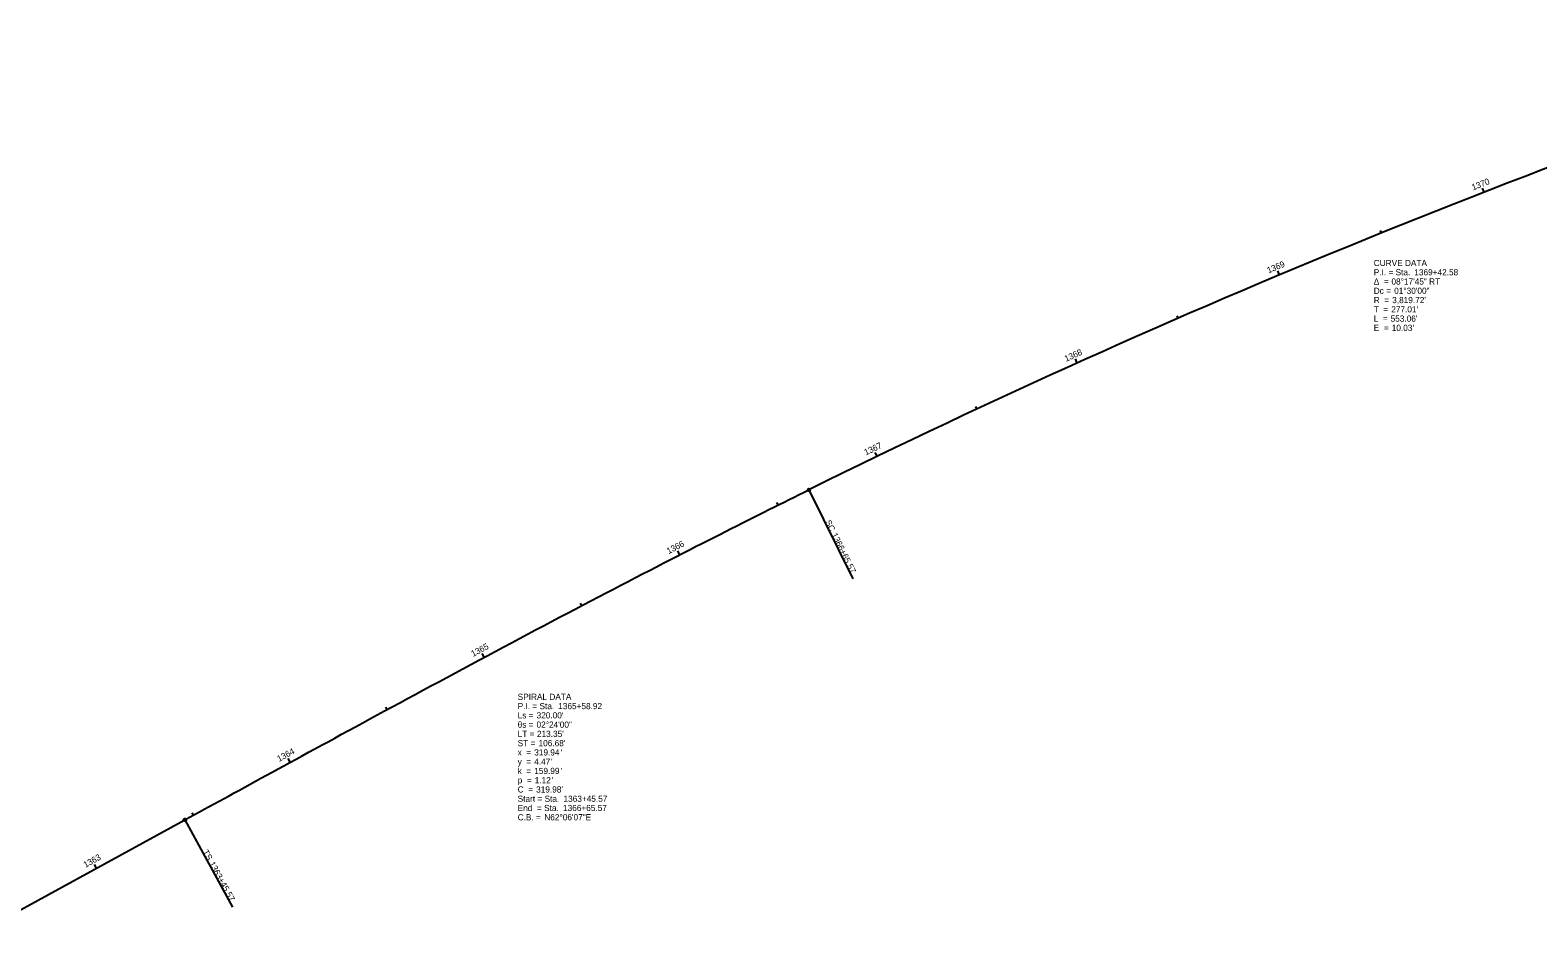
# Model space of a CAD drawing. Extents: x 153500 to 156291, y 370917 to 372075.
# Drawn here: x 154193 to 154876, y 371277 to 371682 of the extents above; entities that cross this region are included whole.
import ezdxf

# ---------------------------------------------------------------- set-up
doc = ezdxf.new("R2010")
doc.units = 0
for name, color, linetype in [('Default', 7, 'Continuous'), ('GE_X_Alignment', 7, 'Continuous'), ('GE_X_Alignment_1000_Curve_Data', 7, 'Continuous'), ('GE_X_Alignment_1000_Stations', 7, 'Continuous'), ('GE_X_Alignment_100_Curve_Data', 7, 'Continuous'), ('GE_X_Alignment_100_Stations', 7, 'Continuous'), ('GE_X_Alignment_500_Curve_Data', 7, 'Continuous'), ('GE_X_Alignment_500_Stations', 7, 'Continuous')]:
    doc.layers.add(name, color=color, linetype=linetype)

msp = doc.modelspace()

# ---------------------------------------------------------------- linework, layer by layer
at = {"layer": 'Default'}
msp.add_line((153521.23, 370917.9), (154262.92, 371323.93), dxfattribs=at)
msp.add_arc((156238, 368049.26), 3819.72, 108.0022, 116.29803, dxfattribs=at)
msp.add_open_spline([(154262.92, 371323.93), (154274.62, 371330.33), (154298.01, 371343.14), (154344.82, 371368.69), (154403.47, 371400.39), (154462.44, 371431.49), (154509.91, 371455.8), (154533.76, 371467.74), (154545.71, 371473.65)], degree=3, dxfattribs=at)
at = {"layer": 'GE_X_Alignment'}
msp.add_line((153521.23, 370917.9), (154262.92, 371323.93), dxfattribs=at)
msp.add_arc((156238, 368049.26), 3819.72, 108.0022, 116.29803, dxfattribs=at)
msp.add_open_spline([(154262.92, 371323.93), (154274.62, 371330.33), (154298.01, 371343.14), (154344.82, 371368.69), (154403.47, 371400.39), (154462.44, 371431.49), (154509.91, 371455.8), (154533.76, 371467.74), (154545.71, 371473.65)], degree=3, dxfattribs=at)
at = {"layer": 'GE_X_Alignment_1000_Stations'}
for p, q in [((154851.63, 371608.51), (154850.9, 371610.37)), ((154545.71, 371473.65), (154565.65, 371433.3)), ((154398.62, 371397.65), (154398.06, 371398.7)), ((154262.92, 371323.93), (154284.53, 371284.46))]:
    msp.add_line(p, q, dxfattribs=at)
for centre in [(154545.71, 371473.65), (154262.92, 371323.93)]:
    msp.add_circle(centre, 0.6, dxfattribs=at)
at = {"layer": 'GE_X_Alignment_100_Stations'}
for p, q in [((154851.63, 371608.51), (154850.9, 371610.37)), ((154805.16, 371590.06), (154804.71, 371591.17)), ((154758.93, 371571), (154758.16, 371572.84)), ((154712.96, 371551.33), (154712.48, 371552.43)), ((154667.25, 371531.07), (154666.43, 371532.9)), ((154621.81, 371510.21), (154621.3, 371511.3)), ((154576.65, 371488.76), (154575.78, 371490.56)), ((154545.71, 371473.65), (154565.65, 371433.3)), ((154531.77, 371466.72), (154531.23, 371467.79)), ((154487.16, 371444.13), (154486.25, 371445.91)), ((154442.8, 371421.07), (154442.24, 371422.13)), ((154398.62, 371397.65), (154397.68, 371399.41)), ((154354.6, 371373.94), (154354.03, 371375)), ((154310.68, 371350.05), (154309.72, 371351.8)), ((154262.92, 371323.93), (154284.53, 371284.46)), ((154266.81, 371326.06), (154266.23, 371327.11)), ((154222.95, 371302.05), (154221.99, 371303.8))]:
    msp.add_line(p, q, dxfattribs=at)
for centre in [(154545.71, 371473.65), (154262.92, 371323.93)]:
    msp.add_circle(centre, 0.6, dxfattribs=at)
at = {"layer": 'GE_X_Alignment_500_Stations'}
for p, q in [((154851.63, 371608.51), (154850.9, 371610.37)), ((154758.93, 371571), (154758.47, 371572.1)), ((154667.25, 371531.07), (154666.76, 371532.17)), ((154576.65, 371488.76), (154576.12, 371489.84)), ((154545.71, 371473.65), (154565.65, 371433.3)), ((154487.16, 371444.13), (154486.61, 371445.2)), ((154398.62, 371397.65), (154397.68, 371399.41)), ((154310.68, 371350.05), (154310.1, 371351.1)), ((154262.92, 371323.93), (154284.53, 371284.46)), ((154222.95, 371302.05), (154222.37, 371303.1))]:
    msp.add_line(p, q, dxfattribs=at)
for centre in [(154545.71, 371473.65), (154262.92, 371323.93)]:
    msp.add_circle(centre, 0.6, dxfattribs=at)

# ---------------------------------------------------------------- texts
at = {"layer": 'GE_X_Alignment_1000_Curve_Data'}
for s, p in [('CURVE DATA', (154801.61, 371575.02)), ('Δ  = ', (154801.61, 371566.62)), ('P.I. = Sta. ', (154801.61, 371570.82)), ('08°17\'45" RT', (154809.63, 371566.62)), ('1369+42.58', (154819.98, 371570.82)), ('Dc = ', (154801.61, 371562.42)), ('01°30\'00"', (154810.85, 371562.42)), ('T  = ', (154801.61, 371554.02)), ('R  = ', (154801.61, 371558.22)), ("277.01'", (154809.54, 371554.02)), ("3,819.72'", (154809.97, 371558.22)), ('L  = ', (154801.61, 371549.82)), ('E  = ', (154801.61, 371545.62)), ("553.06'", (154809.25, 371549.82)), ("10.03'", (154809.76, 371545.62)), ('SPIRAL DATA', (154413.74, 371378.35)), ('P.I. = Sta. ', (154413.74, 371374.15)), ('Ls = ', (154413.74, 371369.95)), ("320.00'", (154422.32, 371369.95)), ('1365+58.92', (154432.1, 371374.15)), ('θs = ', (154413.74, 371365.75)), ('LT = ', (154413.74, 371361.55)), ('02°24\'00"', (154422.27, 371365.75)), ("213.35'", (154422.47, 371361.55)), ('ST = ', (154413.74, 371357.35)), ("106.68'", (154423.19, 371357.35)), ('y  = ', (154413.74, 371348.95)), ('x  = ', (154413.74, 371353.15)), ('4.47', (154421.24, 371348.95)), ('319.94', (154421.24, 371353.15)), ("'", (154428.85, 371348.95)), ("'", (154433.2, 371353.15)), ('k  = ', (154413.74, 371344.75)), ('159.99', (154421.24, 371344.75)), ('1.12', (154421.45, 371340.55)), ("'", (154429.06, 371340.55)), ("'", (154433.2, 371344.75)), ('C  = ', (154413.74, 371336.35)), ('p  = ', (154413.74, 371340.55)), ("319.98'", (154422.1, 371336.35)), ('Start = Sta. ', (154413.74, 371332.15)), ('End  = Sta. ', (154413.74, 371327.95)), ('1366+65.57', (154434.28, 371327.95)), ('1363+45.57', (154434.5, 371332.15)), ('C.B. = ', (154413.74, 371323.75)), ('N62°06\'07"E', (154425.8, 371323.75))]:
    msp.add_text(s, height=2.8, dxfattribs=at).set_placement(p)
at = {"layer": 'GE_X_Alignment_1000_Stations'}
for s, rotation, p in [('1370', 21.28158, (154846.63, 371609.3)), ('SC', 296.29803, (154552.96, 371459.07)), ('1366+65.57', 296.29803, (154555.85, 371453.23)), ('TS', 298.69803, (154270.89, 371309.48)), ('1363+45.57', 298.69803, (154273.81, 371304.14))]:
    msp.add_text(s, height=2.8, rotation=rotation, dxfattribs=at).set_placement(p)
at = {"layer": 'GE_X_Alignment_100_Curve_Data'}
for s, p in [('CURVE DATA', (154801.61, 371575.02)), ('Δ  = ', (154801.61, 371566.62)), ('P.I. = Sta. ', (154801.61, 371570.82)), ('08°17\'45" RT', (154809.63, 371566.62)), ('1369+42.58', (154819.98, 371570.82)), ('Dc = ', (154801.61, 371562.42)), ('01°30\'00"', (154810.85, 371562.42)), ('T  = ', (154801.61, 371554.02)), ('R  = ', (154801.61, 371558.22)), ("277.01'", (154809.54, 371554.02)), ("3,819.72'", (154809.97, 371558.22)), ('L  = ', (154801.61, 371549.82)), ('E  = ', (154801.61, 371545.62)), ("553.06'", (154809.25, 371549.82)), ("10.03'", (154809.76, 371545.62)), ('SPIRAL DATA', (154413.74, 371378.35)), ('P.I. = Sta. ', (154413.74, 371374.15)), ('Ls = ', (154413.74, 371369.95)), ("320.00'", (154422.32, 371369.95)), ('1365+58.92', (154432.1, 371374.15)), ('θs = ', (154413.74, 371365.75)), ('LT = ', (154413.74, 371361.55)), ('02°24\'00"', (154422.27, 371365.75)), ("213.35'", (154422.47, 371361.55)), ('ST = ', (154413.74, 371357.35)), ("106.68'", (154423.19, 371357.35)), ('y  = ', (154413.74, 371348.95)), ('x  = ', (154413.74, 371353.15)), ('4.47', (154421.24, 371348.95)), ('319.94', (154421.24, 371353.15)), ("'", (154428.85, 371348.95)), ("'", (154433.2, 371353.15)), ('k  = ', (154413.74, 371344.75)), ('159.99', (154421.24, 371344.75)), ('1.12', (154421.45, 371340.55)), ("'", (154429.06, 371340.55)), ("'", (154433.2, 371344.75)), ('C  = ', (154413.74, 371336.35)), ('p  = ', (154413.74, 371340.55)), ("319.98'", (154422.1, 371336.35)), ('Start = Sta. ', (154413.74, 371332.15)), ('End  = Sta. ', (154413.74, 371327.95)), ('1366+65.57', (154434.28, 371327.95)), ('1363+45.57', (154434.5, 371332.15)), ('C.B. = ', (154413.74, 371323.75)), ('N62°06\'07"E', (154425.8, 371323.75))]:
    msp.add_text(s, height=2.8, dxfattribs=at).set_placement(p)
at = {"layer": 'GE_X_Alignment_100_Stations'}
for s, rotation, p in [('1370', 21.28158, (154846.63, 371609.3)), ('1369', 22.78158, (154753.94, 371571.66)), ('1368', 24.28158, (154662.22, 371531.6)), ('1367', 25.78158, (154571.55, 371489.13)), ('SC', 296.29803, (154552.96, 371459.07)), ('1366+65.57', 296.29803, (154555.85, 371453.23)), ('1366', 27.18081, (154482.11, 371444.4)), ('1365', 28.13908, (154393.56, 371397.83)), ('1364', 28.6286, (154305.66, 371350.21)), ('TS', 298.69803, (154270.89, 371309.48)), ('1363', 28.69803, (154217.91, 371302.19)), ('1363+45.57', 298.69803, (154273.81, 371304.14))]:
    msp.add_text(s, height=2.8, rotation=rotation, dxfattribs=at).set_placement(p)
at = {"layer": 'GE_X_Alignment_500_Curve_Data'}
for s, p in [('CURVE DATA', (154801.61, 371575.02)), ('Δ  = ', (154801.61, 371566.62)), ('P.I. = Sta. ', (154801.61, 371570.82)), ('08°17\'45" RT', (154809.63, 371566.62)), ('1369+42.58', (154819.98, 371570.82)), ('Dc = ', (154801.61, 371562.42)), ('01°30\'00"', (154810.85, 371562.42)), ('T  = ', (154801.61, 371554.02)), ('R  = ', (154801.61, 371558.22)), ("277.01'", (154809.54, 371554.02)), ("3,819.72'", (154809.97, 371558.22)), ('L  = ', (154801.61, 371549.82)), ('E  = ', (154801.61, 371545.62)), ("553.06'", (154809.25, 371549.82)), ("10.03'", (154809.76, 371545.62)), ('SPIRAL DATA', (154413.74, 371378.35)), ('P.I. = Sta. ', (154413.74, 371374.15)), ('Ls = ', (154413.74, 371369.95)), ("320.00'", (154422.32, 371369.95)), ('1365+58.92', (154432.1, 371374.15)), ('θs = ', (154413.74, 371365.75)), ('LT = ', (154413.74, 371361.55)), ('02°24\'00"', (154422.27, 371365.75)), ("213.35'", (154422.47, 371361.55)), ('ST = ', (154413.74, 371357.35)), ("106.68'", (154423.19, 371357.35)), ('y  = ', (154413.74, 371348.95)), ('x  = ', (154413.74, 371353.15)), ('4.47', (154421.24, 371348.95)), ('319.94', (154421.24, 371353.15)), ("'", (154428.85, 371348.95)), ("'", (154433.2, 371353.15)), ('k  = ', (154413.74, 371344.75)), ('159.99', (154421.24, 371344.75)), ('1.12', (154421.45, 371340.55)), ("'", (154429.06, 371340.55)), ("'", (154433.2, 371344.75)), ('C  = ', (154413.74, 371336.35)), ('p  = ', (154413.74, 371340.55)), ("319.98'", (154422.1, 371336.35)), ('Start = Sta. ', (154413.74, 371332.15)), ('End  = Sta. ', (154413.74, 371327.95)), ('1366+65.57', (154434.28, 371327.95)), ('1363+45.57', (154434.5, 371332.15)), ('C.B. = ', (154413.74, 371323.75)), ('N62°06\'07"E', (154425.8, 371323.75))]:
    msp.add_text(s, height=2.8, dxfattribs=at).set_placement(p)
at = {"layer": 'GE_X_Alignment_500_Stations'}
for s, rotation, p in [('1370', 21.28158, (154846.63, 371609.3)), ('SC', 296.29803, (154552.96, 371459.07)), ('1366+65.57', 296.29803, (154555.85, 371453.23)), ('1365', 28.13908, (154393.56, 371397.83)), ('TS', 298.69803, (154270.89, 371309.48)), ('1363+45.57', 298.69803, (154273.81, 371304.14))]:
    msp.add_text(s, height=2.8, rotation=rotation, dxfattribs=at).set_placement(p)

doc.saveas('drawing.dxf')
